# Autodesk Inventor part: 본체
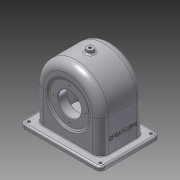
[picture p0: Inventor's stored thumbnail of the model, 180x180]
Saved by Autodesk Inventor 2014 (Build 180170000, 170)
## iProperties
Created: 2016-01
Part Number: 본체
Material: 알루미늄 6061
Document SubType Name: 판금
Designer: SCD-A15
Density: 2.71 g/cm^3
Appearance: 알루미늄 - 평지
Sheet Metal Rule: 기본값
Mass: 912.796 g
Surface Area: 1098.08 cm^2
Volume: 336.825 cm^3
Author: SCD-A15
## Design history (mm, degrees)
sketch "스케치1"
  geometry: L1 (-70, 52)-(70, 52); L2 (70, 52)-(70, -52); L3 (70, -52)-(-70, -52); L4 (-70, -52)-(-70, 52); 3 further points
  constraints: 8 end point, 2 midpoint, 2 parallel, 1 horizontal, 1 horizontal alignment, 1 perpendicular, 1 vertical alignment
  dimensions: "d0" = 140 distance of L1.start L1.end; "d1" = 104 distance of L1.end L2.end
extrude "돌출1" new body sketch "스케치1" distance "d2" = 7; taper "d3" = 0 deg
node "작업 평면1"
sketch "스케치3"
  geometry: L1 (-43, 38.5)-(43, 38.5); L2 (57, 24.5)-(57, -24.5); L3 (43, -38.5)-(-43, -38.5); L4 (-57, -24.5)-(-57, 24.5); L5 (-42, 33.5)-(42, 33.5); L6 (51, 24.5)-(51, -24.5); L7 (42, -33.5)-(-42, -33.5); L8 (-51, -24.5)-(-51, 24.5); L9 (0, 33.5)-(0, -33.5); L10 (0, 38.5)-(0, 33.5); L11 (0, -33.5)-(0, -38.5); A1 r 9 centre (-42, 24.5) between (-42, 33.5) and (-51, 24.5); A2 r 9 centre (-42, -24.5) between (-51, -24.5) and (-42, -33.5); A3 r 9 centre (42, -24.5) between (42, -33.5) and (51, -24.5); A4 r 9 centre (42, 24.5) between (51, 24.5) and (42, 33.5); A5 r 14 centre (-43, 24.5) between (-43, 38.5) and (-57, 24.5); A6 r 14 centre (-43, -24.5) between (-57, -24.5) and (-43, -38.5); A7 r 14 centre (43, -24.5) between (43, -38.5) and (57, -24.5); A8 r 14 centre (43, 24.5) between (57, 24.5) and (43, 38.5); 2 further points
  constraints: 22 end point, 16 point on circle, 16 tangent, 8 centre point, 6 equal radius, 5 midpoint, 4 parallel, 3 perpendicular, 2 horizontal, 1 collinear, 1 horizontal alignment, 1 vertical alignment
  dimensions: "d14" = 9 radius of A1; "d15" = 14 radius of A5; "d16" = 6 distance between parallel lines of L4 L8; "d17" = 6 distance between parallel lines of L2 L6; "d18" = 5 distance between parallel lines of L1 L5; "d19" = 5 distance between parallel lines of L3 L7; "d20" = 77 distance between parallel lines of L3 L1; "d21" = 114 distance between parallel lines of L4 L2
extrude "돌출2" join sketch "스케치3" stored distance "d22" = 64; taper "d23" = 0 deg
revolve "회전4" stored, may be unused: angle "d116" = 90 deg
sketch "스케치18"
  geometry: L1 (-27, 7)-(113, 7) reference; C1 r 31 at (43, -53); A1 r 43 centre (43, -57) between (0, -57) and (86, -57) reference; 1 further point
  constraints: 1 centre point, 1 vertical alignment
  dimensions: "d117" = 62 diameter of C1; "d118" = 60 distance from line of L1 C1.centre
extrude "돌출5" join sketch "스케치18" distance "d119" = 10; taper "d120" = 0 deg
sketch "스케치19"
  geometry: L1 (-38.5, 60)-(33.5, 60); L2 (-38.5, 64)-(-38.5, 107) reference; L3 (-38.5, 64)-(-38.5, 7) reference; L4 (33.5, 64)-(33.5, 7) reference; L5 (33.5, 64)-(33.5, 106) reference; L6 (-35.5, 60)-(-35.5, 94.899); L7 (-19.5, 60)-(-19.5, 88); L8 (-24.729, 106)-(33.5, 106); L9 (-35.5, 80)-(-19.5, 80); L10 (-19.5, 88)-(-33.5, 99.747); L11 (-35.5, 94.899)-(-38.5, 97.416); L12 (-33.5, 99.747)-(-33.5, 106); L13 (-33.5, 106)-(-24.729, 106); L14 (33.5, 106)-(33.5, 60); L15 (-33.5, 99.747)-(-35.5, 94.899); 1 further point
  constraints: 22 end point, 7 point on line, 4 parallel, 2 perpendicular, 1 collinear, 1 horizontal
  dimensions: "d142" = 3 distance between parallel lines of L2 L6; "d143" = 5 distance between parallel lines of L2 L12; "d144" = 56 diameter of L7.end L1; "d146" = 16 distance between parallel lines of L6 L7; "d148" = 50 deg angle of L7 L10; "d150" = 5 distance between parallel lines of L10 L11; "d151" = 40 diameter of L9 L1
revolve "회전7" stored, may be unused: angle "d153" = 90 deg
node "작업 평면5"
  node "작업 평면4"
sketch "스케치24"
  geometry: C1 r 6 at (0, 0); 1 further point
  constraints: 1 centre point, 1 coincident
  dimensions: "d155" = 12 diameter of C1
extrude "돌출6" join sketch "스케치24" stored distance "d156" = 5; taper "d157" = 0 deg
revolve "회전8" stored, may be unused: angle "d158" = 90 deg
hole "구멍6" diameter "d161" = 40; stored, may be unused: countersink angle "d165" = 90 deg, drill point angle "d167" = 0 deg; dims "d159" = 10, "d160" = 10, "d162" = 6, "d163" = 4, "d164" = 2, "d166" = 5
sketch "스케치25"
  geometry: L1 (7, 76.5)-(7, -27.5) reference; L2 (-57, -14)-(0, -14) reference; 2 further points
  constraints: 1 other
  dimensions: "d168" = 30 distance from line of point (-23, 24.5) L1; "d169" = 38.5 distance from line of L2 point (-23, 24.5)
feature "엠보싱2" sketch "스케치25" dims "d14" = 9, "d15" = 14, "d16" = 6, "d17" = 6, "d18" = 5, "d19" = 5, "d20" = 77, "d21" = 114, "d170" = 0.5, "d171" = 0
sketch "스케치27" dims "d172" = 56
  geometry: C1 r 34.899 at (0, 0) reference; 3 further points
  constraints: 1 coincident, 1 vertical alignment, 2 other
hole "구멍7" sketch "스케치27" at (0, 28) diameter "d173" = 2.459; stored, may be unused: countersink angle "d177" = 90 deg, drill point angle "d179" = 118 deg; dims "d174" = 7, "d175" = 4, "d176" = 2, "d178" = 9
sketch "스케치28" dims "d183" = 48
  geometry: C1 r 31 at (0, 0) reference; 3 further points
  constraints: 1 coincident, 1 vertical alignment, 2 other
hole "구멍8" sketch "스케치28" at (0, 24) diameter "d184" = 2.459; stored, may be unused: countersink angle "d188" = 90 deg, drill point angle "d190" = 118 deg; dims "d185" = 6, "d186" = 4, "d187" = 2, "d189" = 8
hole "구멍9" diameter "d196" = 40; stored, may be unused: countersink angle "d200" = 90 deg, drill point angle "d202" = 0 deg; dims "d194" = 10, "d195" = 10, "d197" = 6, "d198" = 4, "d199" = 2, "d201" = 32
fillet "모깎기6" dims "d203" = 8
sketch "스케치29"
  geometry: A1 r 8 centre (-62, 44) between (-62, 52) and (-70, 44) reference; A2 r 8 centre (-62, -44) between (-70, -44) and (-62, -52) reference; A3 r 8 centre (62, -44) between (62, -52) and (70, -44) reference; A4 r 8 centre (62, 44) between (70, 44) and (62, 52) reference; 1 further point
hole "구멍10" sketch "스케치29" at (-62, -44), (62, -44), (62, 44), (-62, 44) diameter "d204" = 5; stored, may be unused: countersink angle "d208" = 90 deg, drill point angle "d210" = 0 deg; dims "d205" = 6, "d206" = 4, "d207" = 2, "d209" = 32
hole "구멍11" diameter "d213" = 4.459; stored, may be unused: countersink angle "d217" = 90 deg, drill point angle "d219" = 0 deg; dims "d214" = 6, "d215" = 4, "d216" = 2, "d218" = 46.5, "d233" = 10, "d234" = 10
fillet "모깎기7" dims "d220" = 1
fillet "모깎기8" dims "d221" = 3
fillet "모깎기9" dims "d222" = 3
chamfer "모따기1" distance "d223" = 1; stored, may be unused: second distance "d224" = 2, angle "d225" = 45 deg
chamfer "모따기2" distance "d226" = 1; stored, may be unused: second distance "d227" = 2, angle "d228" = 45 deg
chamfer "모따기3" distance "d229" = 1; stored, may be unused: second distance "d230" = 2, angle "d231" = 45 deg
fillet "모깎기10" dims "d232" = 3
sketch "스케치30"
  geometry: 1 further point
node "솔리드1"
pattern_circular "원형 패턴3" dims angle "d181" = 360 deg
pattern_circular "원형 패턴4" dims angle "d192" = 360 deg
other parameters: "d13" = 57, "K계수" = 4.4, "BendRadius" = 0.5 (derived), "BendReliefWidth" = 0.5 (derived), "BendReliefDepth" = 0.25 (derived), "CornerReliefSize" = 2 (derived), "SeamGap" = 0.01, "MinimumRemnant" = 1 (derived), "TransitionRadius" = 0.5 (= BendRadius), "d132" = 50 deg, "d154" = 6
